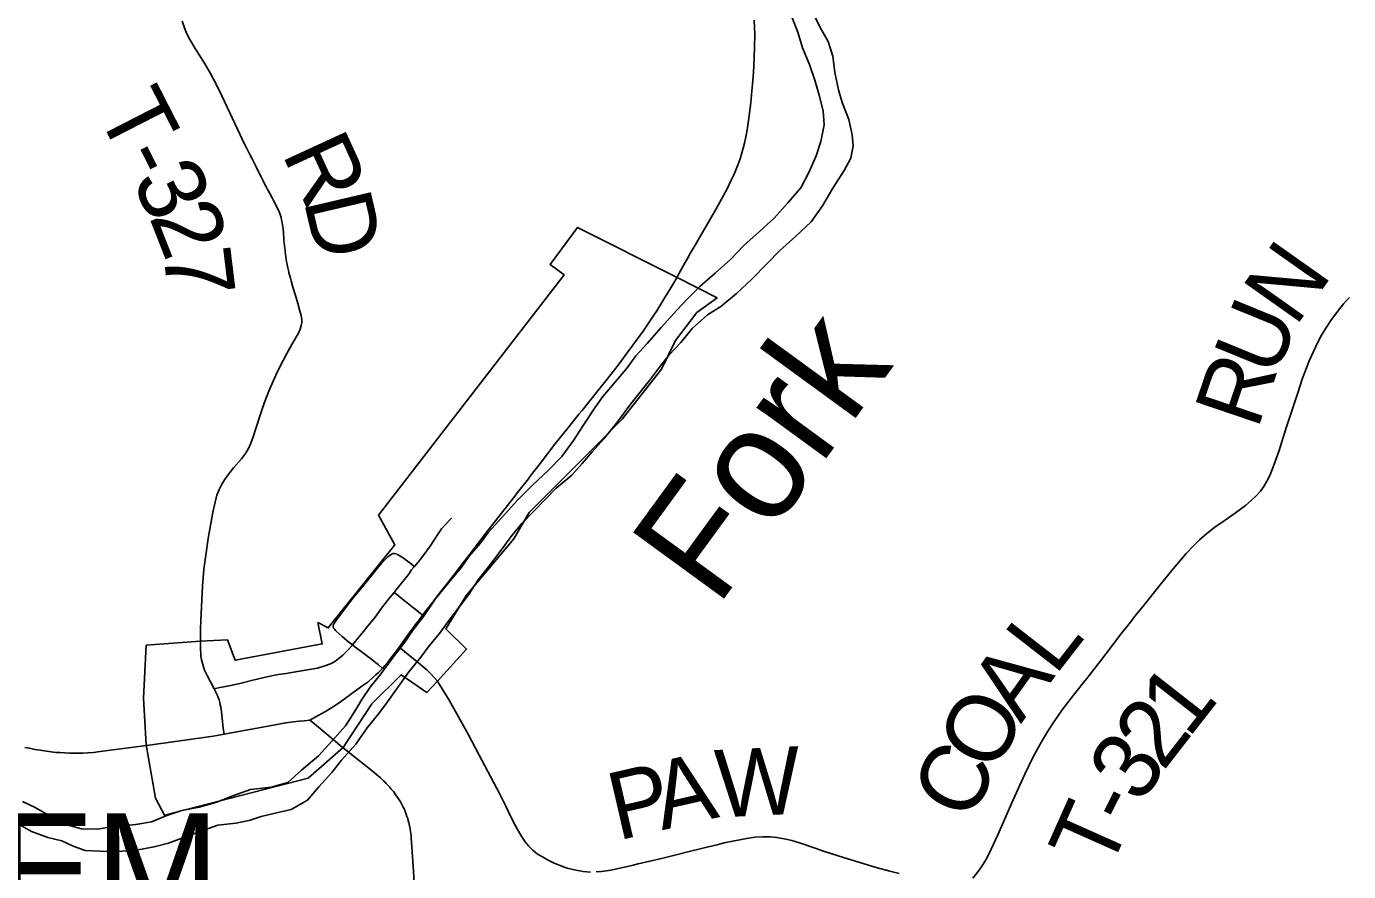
# Model space of a CAD drawing. Extents: x 0 to 34, y 0 to 22.
# Drawn here: x 4.132 to 5.245, y 14.51 to 15.221 of the extents above; entities that cross this region are included whole.
import ezdxf

# ---------------------------------------------------------------- set-up
doc = ezdxf.new("R2010")
doc.units = 0
for name, color, linetype in [('GM_X_City_Street', 7, 'Continuous'), ('GM_X_Corporation_Text', 7, 'Continuous'), ('GM_X_Major_River', 7, 'Continuous'), ('GM_X_Major_River_Text', 7, 'Continuous'), ('GM_X_State_Route', 7, 'Continuous'), ('GM_X_Township_Road', 7, 'Continuous'), ('GM_X_Township_Road_Text', 7, 'Continuous'), ('GM_X_Township_Text', 7, 'Continuous')]:
    doc.layers.add(name, color=color, linetype=linetype)

msp = doc.modelspace()

# ---------------------------------------------------------------- linework, layer by layer
at = {"layer": 'GM_X_City_Street'}
for points in [[(4.2896, 14.6637), (4.2945, 14.6648), (4.3023, 14.6664), (4.3113, 14.6683), (4.3222, 14.671), (4.3355, 14.6742), (4.3434, 14.6758), (4.3502, 14.6768), (4.3582, 14.678), (4.3765, 14.6813), (4.3819, 14.6828), (4.3877, 14.6849), (4.3905, 14.6863), (4.3936, 14.6884), (4.3979, 14.692), (4.4023, 14.6964), (4.4055, 14.7001), (4.406, 14.7007), (4.4086, 14.704), (4.4127, 14.7087), (4.4155, 14.712), (4.4186, 14.716), (4.4252, 14.7242), (4.4315, 14.7327), (4.4379, 14.741), (4.4412, 14.745), (4.4437, 14.7482), (4.451, 14.7573), (4.4532, 14.7601), (4.4544, 14.7618), (4.4556, 14.7636), (4.4581, 14.7666), (4.4615, 14.7705), (4.4646, 14.7743), (4.4715, 14.7839), (4.4776, 14.7933), (4.4812, 14.7984), (4.4844, 14.8022), (4.4887, 14.8066), (4.4896, 14.8075)], [(4.3899, 14.7169), (4.3902, 14.718), (4.3905, 14.7186), (4.3911, 14.7196), (4.3922, 14.7211), (4.4003, 14.732), (4.4068, 14.7403), (4.4143, 14.7493), (4.4268, 14.765), (4.4282, 14.7667), (4.43, 14.7687), (4.4312, 14.7702), (4.4327, 14.7718), (4.4341, 14.7733), (4.4358, 14.7748), (4.4366, 14.7755), (4.4372, 14.776), (4.4378, 14.7764), (4.4387, 14.7769), (4.4395, 14.7773), (4.4405, 14.7777), (4.4416, 14.7777), (4.4427, 14.7774), (4.4436, 14.7771), (4.4443, 14.7767), (4.4451, 14.7762), (4.4459, 14.7757), (4.447, 14.775), (4.4478, 14.7746), (4.4525, 14.7713), (4.4543, 14.7699), (4.4574, 14.7672), (4.4581, 14.7666)], [(4.4412, 14.745), (4.4431, 14.7435), (4.4468, 14.7405), (4.4522, 14.7362), (4.4579, 14.7316), (4.4631, 14.7274), (4.4652, 14.7258)], [(4.3899, 14.7169), (4.3899, 14.7157), (4.3904, 14.7146), (4.3912, 14.7136), (4.3918, 14.713), (4.3924, 14.7123), (4.3974, 14.7077), (4.403, 14.703), (4.406, 14.7007), (4.4082, 14.699), (4.4146, 14.6945), (4.4214, 14.6894), (4.4266, 14.6851), (4.4276, 14.6843), (4.4313, 14.681)]]:
    msp.add_lwpolyline(points, dxfattribs=at)
at = {"layer": 'GM_X_Major_River'}
for points in [[(4.122, 14.5515), (4.1357, 14.5437), (4.1495, 14.5386), (4.1613, 14.5357), (4.1708, 14.5313), (4.1811, 14.5276), (4.1936, 14.5271), (4.2057, 14.5268), (4.2186, 14.5274), (4.2288, 14.5287), (4.2402, 14.5311), (4.2511, 14.5339), (4.2647, 14.539), (4.2779, 14.5438), (4.2926, 14.5489), (4.3078, 14.5506), (4.3191, 14.553), (4.3293, 14.5562), (4.341, 14.559), (4.3546, 14.5622), (4.3682, 14.57), (4.3779, 14.5812), (4.3887, 14.5934), (4.3969, 14.6038), (4.4089, 14.6172), (4.4185, 14.631), (4.4282, 14.6429), (4.4357, 14.6529), (4.4431, 14.6636), (4.4535, 14.6782), (4.4636, 14.6905), (4.4707, 14.7), (4.4793, 14.7104), (4.4875, 14.7215), (4.4964, 14.7334), (4.5038, 14.743), (4.512, 14.7556), (4.5206, 14.7664), (4.5321, 14.7817), (4.5403, 14.7928), (4.5489, 14.8032), (4.5777, 14.8328), (4.5908, 14.8436), (4.5994, 14.8536), (4.608, 14.8632), (4.6177, 14.8743), (4.6285, 14.8874), (4.6404, 14.9038), (4.6483, 14.9134), (4.6561, 14.9234), (4.6647, 14.9345), (4.6729, 14.9449), (4.6826, 14.9553), (4.6923, 14.9671), (4.705, 14.9787), (4.7163, 14.9857), (4.7294, 14.9965), (4.7422, 15.0084), (4.7552, 15.0219), (4.7661, 15.0327), (4.7792, 15.0446), (4.7923, 15.0569), (4.802, 15.0703), (4.8105, 15.0852), (4.8202, 15.1002), (4.8257, 15.1105), (4.8278, 15.1208), (4.827, 15.1302), (4.8241, 15.1431), (4.8186, 15.1574), (4.8155, 15.168), (4.8122, 15.1828), (4.8105, 15.1964), (4.8066, 15.2089), (4.8, 15.2206), (4.7898, 15.2409)], [(4.7763, 15.2286), (4.7811, 15.2165), (4.785, 15.2033), (4.7909, 15.1893), (4.7956, 15.1761), (4.7992, 15.1636), (4.8024, 15.1504), (4.8033, 15.1386), (4.8005, 15.1246), (4.7965, 15.1124), (4.7906, 15.099), (4.7836, 15.0856), (4.7728, 15.073), (4.7612, 15.0599), (4.7488, 15.0487), (4.7353, 15.0368), (4.7245, 15.0253), (4.7114, 15.0137), (4.6986, 15.0025), (4.6882, 14.9921), (4.6792, 14.9825), (4.6661, 14.9679), (4.6542, 14.9545), (4.6448, 14.9441), (4.6374, 14.9341), (4.6284, 14.9234), (4.6169, 14.91), (4.6102, 14.9004), (4.6009, 14.8862), (4.5923, 14.8728), (4.5823, 14.8594), (4.5711, 14.8479), (4.5576, 14.8352), (4.5452, 14.8225), (4.5322, 14.8083), (4.5206, 14.7956), (4.5135, 14.786), (4.5045, 14.7756), (4.4978, 14.7661), (4.487, 14.753), (4.4758, 14.7392), (4.4658, 14.7246), (4.4572, 14.7135), (4.4494, 14.702), (4.4405, 14.6905), (4.4293, 14.6756), (4.4211, 14.6652), (4.414, 14.6549), (4.4081, 14.6449), (4.4003, 14.6327), (4.3891, 14.62), (4.3775, 14.6073), (4.3633, 14.5954), (4.3517, 14.585), (4.3377, 14.581), (4.3203, 14.5789), (4.3052, 14.5737), (4.2909, 14.5682), (4.2769, 14.5642), (4.2625, 14.5614), (4.2497, 14.557), (4.2369, 14.5519), (4.2236, 14.5495), (4.2032, 14.5477), (4.1915, 14.5456), (4.1778, 14.5458), (4.1656, 14.5494), (4.1526, 14.5561), (4.1389, 14.5639), (4.1282, 14.569)]]:
    msp.add_lwpolyline(points, dxfattribs=at)
at = {"layer": 'GM_X_State_Route'}
for points in [[(4.6792, 15.0099), (4.6809, 15.0131), (4.6827, 15.0163), (4.6851, 15.0206), (4.6882, 15.026), (4.6909, 15.0309), (4.6947, 15.0373), (4.6981, 15.0432), (4.7028, 15.0513), (4.7123, 15.068), (4.7172, 15.0766), (4.7216, 15.0848), (4.7251, 15.092), (4.7273, 15.0965), (4.7287, 15.0999), (4.731, 15.1056), (4.7325, 15.1101), (4.734, 15.1151), (4.7351, 15.1191), (4.7361, 15.1233), (4.737, 15.1271), (4.7378, 15.1312), (4.7387, 15.136), (4.7402, 15.1464), (4.7412, 15.155), (4.7419, 15.1605), (4.7425, 15.1673), (4.743, 15.1729), (4.7434, 15.1791), (4.744, 15.1877), (4.7447, 15.2038), (4.7448, 15.2149), (4.7447, 15.2205), (4.7444, 15.2266)], [(4.3703, 14.6374), (4.3773, 14.6412), (4.3835, 14.6446), (4.3906, 14.6491), (4.3959, 14.6528), (4.414, 14.6659), (4.4189, 14.6695), (4.4232, 14.6732), (4.4258, 14.6755), (4.4277, 14.6773), (4.4313, 14.681), (4.4334, 14.6835), (4.4358, 14.6863), (4.4393, 14.6906), (4.4423, 14.6947), (4.4448, 14.6981), (4.4454, 14.6989), (4.447, 14.7011), (4.4513, 14.7072), (4.4558, 14.7132), (4.4593, 14.718), (4.4624, 14.7222), (4.4652, 14.7258), (4.4734, 14.7365), (4.4805, 14.7457), (4.486, 14.7528), (4.4912, 14.7593), (4.498, 14.7682), (4.5041, 14.7761), (4.5185, 14.7948), (4.5417, 14.8246), (4.5463, 14.8305), (4.5542, 14.8407), (4.5558, 14.8427), (4.5641, 14.8534), (4.5766, 14.8697), (4.5887, 14.8847), (4.5968, 14.8949), (4.5995, 14.8982), (4.6125, 14.9144), (4.6207, 14.9245), (4.6298, 14.9362), (4.6367, 14.9456), (4.6423, 14.953), (4.6468, 14.9592), (4.6504, 14.9641), (4.6532, 14.9682), (4.6594, 14.9774), (4.6624, 14.9821), (4.6692, 14.9932), (4.6741, 15.0013), (4.6792, 15.0099)], [(4.3703, 14.6374), (4.3655, 14.6369), (4.3613, 14.6366), (4.3564, 14.636), (4.3499, 14.6352), (4.3366, 14.6327), (4.3211, 14.6299), (4.2979, 14.6256), (4.2887, 14.6239), (4.263, 14.6203), (4.2409, 14.6172), (4.2325, 14.616)], [(4.3978, 14.6145), (4.3936, 14.6181), (4.3846, 14.6255), (4.3741, 14.6342), (4.3703, 14.6374)], [(4.1707, 14.6096), (4.1681, 14.6096), (4.1638, 14.6098), (4.16, 14.6101), (4.1563, 14.6103), (4.1523, 14.6107), (4.1485, 14.6112), (4.143, 14.6121), (4.1385, 14.6128), (4.134, 14.6137), (4.1303, 14.6145)], [(4.2325, 14.616), (4.1936, 14.6109), (4.1881, 14.6103), (4.1831, 14.6099), (4.179, 14.6097), (4.1756, 14.6096), (4.1716, 14.6096), (4.1707, 14.6096)], [(4.4594, 14.4752), (4.4574, 14.5103), (4.4565, 14.5266), (4.4556, 14.5383), (4.4555, 14.5402), (4.4552, 14.5421), (4.455, 14.5437), (4.4547, 14.5458), (4.4545, 14.547), (4.4542, 14.5484), (4.4539, 14.5498), (4.4535, 14.5512), (4.4531, 14.5527), (4.4526, 14.5545), (4.452, 14.5564), (4.451, 14.5592), (4.4505, 14.5604), (4.4501, 14.5615), (4.4495, 14.5628), (4.4489, 14.5641), (4.4477, 14.5665), (4.4465, 14.5685), (4.4449, 14.5712), (4.4435, 14.5732), (4.4417, 14.5757), (4.4408, 14.577), (4.4396, 14.5784), (4.4385, 14.5797), (4.4372, 14.5813), (4.436, 14.5827), (4.4346, 14.5841), (4.4333, 14.5854), (4.4319, 14.5867), (4.4296, 14.5889), (4.4264, 14.5916), (4.4184, 14.5981), (4.4095, 14.6052), (4.4036, 14.6099), (4.3985, 14.6139), (4.3978, 14.6145)]]:
    msp.add_lwpolyline(points, dxfattribs=at)
at = {"layer": 'GM_X_Township_Road'}
for points in [[(4.2782, 14.714), (4.2785, 14.7212), (4.2799, 14.7503), (4.281, 14.7645), (4.2822, 14.7744), (4.2847, 14.7904), (4.2886, 14.8124), (4.2904, 14.8209), (4.292, 14.8269), (4.2938, 14.8315), (4.2957, 14.8354), (4.2982, 14.8397), (4.3019, 14.8447), (4.3062, 14.85), (4.3127, 14.8575), (4.316, 14.862), (4.3185, 14.8662), (4.3206, 14.8707), (4.3225, 14.8759), (4.3247, 14.883), (4.3285, 14.8949), (4.3318, 14.9043), (4.3363, 14.9158), (4.3416, 14.9278), (4.345, 14.935), (4.3504, 14.9455), (4.3552, 14.9542), (4.3606, 14.9632), (4.3621, 14.9666), (4.363, 14.9696), (4.3634, 14.972), (4.3635, 14.9745), (4.3629, 14.9781), (4.3616, 14.9829), (4.36, 14.9883), (4.358, 14.9948), (4.356, 15.0019), (4.3545, 15.0072), (4.3538, 15.0095), (4.3526, 15.0142), (4.3522, 15.016), (4.3516, 15.0183), (4.3514, 15.0194), (4.351, 15.0212), (4.3506, 15.0235), (4.3503, 15.0252), (4.3499, 15.0276), (4.3497, 15.0298), (4.3495, 15.0315), (4.3493, 15.0326), (4.3491, 15.0348), (4.3488, 15.0365), (4.3488, 15.0376), (4.3487, 15.0387), (4.3484, 15.0414), (4.3482, 15.0442), (4.348, 15.0459), (4.348, 15.0476), (4.3477, 15.051), (4.3473, 15.0544), (4.3469, 15.0561), (4.3467, 15.0573), (4.346, 15.0607), (4.3449, 15.064), (4.344, 15.0662), (4.343, 15.0683), (4.341, 15.0725), (4.3395, 15.075), (4.3384, 15.0771), (4.3364, 15.0807), (4.335, 15.0833), (4.3345, 15.0843), (4.3331, 15.0869), (4.3312, 15.0905), (4.3305, 15.0921), (4.3294, 15.0942), (4.3286, 15.0958), (4.3243, 15.1044), (4.3221, 15.1088), (4.3216, 15.1099), (4.32, 15.1131), (4.3166, 15.1197), (4.3144, 15.1241), (4.3114, 15.1303), (4.2962, 15.163), (4.2907, 15.1741), (4.2854, 15.1839), (4.2809, 15.1914), (4.2736, 15.2029), (4.2692, 15.2104), (4.2664, 15.2159), (4.2643, 15.2211), (4.2628, 15.2258)], [(4.9284, 14.5045), (4.9339, 14.5112), (4.9367, 14.5153), (4.9399, 14.5206), (4.9441, 14.5289), (4.9495, 14.5408), (4.9624, 14.5704), (4.9723, 14.5919), (4.9794, 14.6064), (4.9853, 14.6173), (4.9916, 14.628), (4.997, 14.6364), (5.0038, 14.646), (5.0113, 14.6559), (5.0205, 14.6676), (5.0216, 14.6691), (5.0244, 14.6725), (5.0362, 14.6876), (5.0408, 14.6935), (5.0533, 14.7097), (5.0552, 14.7122), (5.0582, 14.7161), (5.0621, 14.7209), (5.065, 14.7249), (5.0709, 14.7321), (5.0864, 14.7514), (5.0973, 14.7649), (5.1082, 14.7777), (5.1141, 14.784), (5.1194, 14.7892), (5.1255, 14.7945), (5.1324, 14.7998), (5.141, 14.8059), (5.1496, 14.812), (5.1581, 14.8182), (5.1629, 14.8222), (5.1674, 14.8265), (5.1707, 14.8302), (5.1736, 14.8342), (5.1762, 14.8385), (5.1786, 14.8435), (5.1821, 14.8522), (5.1865, 14.8645), (5.1922, 14.8827), (5.2023, 14.9129), (5.206, 14.9244), (5.2118, 14.9399), (5.2174, 14.9519), (5.2214, 14.9602), (5.2258, 14.9674), (5.2301, 14.9738), (5.2357, 14.9814), (5.2406, 14.9879), (5.2435, 14.9911), (5.2457, 14.9933)], [(4.2781, 14.7042), (4.2781, 14.7088), (4.2782, 14.714)], [(4.2896, 14.6637), (4.2836, 14.6751), (4.2824, 14.6777), (4.2816, 14.6796), (4.2806, 14.6822), (4.28, 14.6843), (4.2792, 14.6873), (4.2788, 14.6894), (4.2785, 14.6915), (4.2783, 14.694), (4.2782, 14.6964), (4.278, 14.6987), (4.2781, 14.7007), (4.2781, 14.7032), (4.2781, 14.7042)], [(4.4773, 14.6704), (4.4752, 14.6731), (4.4719, 14.6768), (4.4687, 14.6798), (4.462, 14.6854), (4.45, 14.6951), (4.4454, 14.6989)], [(4.6065, 14.5095), (4.6003, 14.51), (4.5942, 14.511), (4.587, 14.5129), (4.5817, 14.5147), (4.5753, 14.5173), (4.5703, 14.5198), (4.5661, 14.5223), (4.562, 14.5247), (4.558, 14.5279), (4.5542, 14.5315), (4.5515, 14.5351), (4.5486, 14.5393), (4.5451, 14.5454), (4.5418, 14.5515), (4.5376, 14.5603), (4.5353, 14.5651), (4.53, 14.5756), (4.5126, 14.6086), (4.5037, 14.625), (4.4954, 14.6403), (4.4875, 14.6543), (4.4779, 14.6697), (4.4773, 14.6704)], [(4.2979, 14.6256), (4.2973, 14.6303), (4.2963, 14.6391), (4.2957, 14.6443), (4.2955, 14.6463), (4.2952, 14.6482), (4.2948, 14.6503), (4.2943, 14.6524), (4.2937, 14.6544), (4.293, 14.6565), (4.2921, 14.6586), (4.291, 14.6609), (4.2896, 14.6637)], [(4.8664, 14.5083), (4.8586, 14.5102), (4.8472, 14.5133), (4.8306, 14.5184), (4.8151, 14.5232), (4.8027, 14.5272), (4.7957, 14.5296), (4.7833, 14.5338), (4.7762, 14.536), (4.7711, 14.5371), (4.7634, 14.5385), (4.7579, 14.5391), (4.7517, 14.5392), (4.7448, 14.5388), (4.7381, 14.5379), (4.7277, 14.5359), (4.7192, 14.5341), (4.7132, 14.5325), (4.7023, 14.5299), (4.6873, 14.5262), (4.6788, 14.5241), (4.6662, 14.5209), (4.6468, 14.5163), (4.6426, 14.5153), (4.6353, 14.5137), (4.6238, 14.5112), (4.6158, 14.51), (4.6114, 14.5096)]]:
    msp.add_lwpolyline(points, dxfattribs=at)
at = {"layer": 'GM_X_Township_Text'}
msp.add_lwpolyline([(4.377, 14.7196), (4.3857, 14.7151), (4.4418, 14.785), (4.428, 14.81), (4.5845, 15.0122), (4.5727, 15.0209), (4.5957, 15.0523), (4.679, 15.0104), (4.7132, 14.9929), (4.6962, 14.9807), (4.678, 14.9571), (4.6663, 14.933), (4.6333, 14.8909), (4.6087, 14.866), (4.555, 14.8123), (4.5421, 14.79), (4.5022, 14.7426), (4.4848, 14.7143), (4.5022, 14.6972), (4.4777, 14.6702), (4.4688, 14.6607), (4.4472, 14.6755), (4.4225, 14.6511), (4.3983, 14.6145), (4.3688, 14.5885), (4.2478, 14.5573), (4.2403, 14.5716), (4.2323, 14.6165), (4.2302, 14.656), (4.2324, 14.7005), (4.2779, 14.7038), (4.3009, 14.705), (4.3074, 14.6879), (4.3806, 14.7016)], close=True, dxfattribs=at)

# ---------------------------------------------------------------- texts
at = {"layer": 'GM_X_Corporation_Text'}
msp.add_text('LOWER SALEM', height=0.094697, rotation=0, dxfattribs=at).set_placement((3.3656, 14.4642))
at = {"layer": 'GM_X_Major_River_Text'}
msp.add_text('Fork', height=0.09473, rotation=53.9104, dxfattribs=at).set_placement((4.7129, 14.7313))
at = {"layer": 'GM_X_Township_Road_Text'}
for s, rotation, p in [('T', 297.0845, (4.19, 15.15)), ('R', 294.7111, (4.3463, 15.1146)), ('-', 296.8583, (4.2093, 15.1122)), ('3', 295.9041, (4.2197, 15.0916)), ('D', 283.1898, (4.3648, 15.075)), ('2', 291.4874, (4.2346, 15.0612)), ('7', 276.9643, (4.2464, 15.0323)), ('N', 54.7528, (5.2001, 14.9677)), ('U', 67.7366, (5.1828, 14.9244)), ('R', 71.2861, (5.1682, 14.8811)), ('L', 52.1307, (4.9978, 14.6741)), ('A', 54.395, (4.969, 14.6339)), ('1', 51.9904, (5.1101, 14.6214)), ('O', 62.0501, (4.9466, 14.5914)), ('2', 52.1798, (5.0887, 14.5937)), ('3', 55.4569, (5.0694, 14.5656)), ('W', 2.7289, (4.7128, 14.5554)), ('C', 62.6774, (4.9253, 14.5501)), ('P', 13.0658, (4.6294, 14.5359)), ('A', 12.9733, (4.6667, 14.5446)), ('-', 63.3616, (5.0599, 14.5465)), ('T', 65.9426, (5.0429, 14.5083))]:
    msp.add_text(s, height=0.0568, rotation=rotation, dxfattribs=at).set_placement(p)

doc.saveas('drawing.dxf')
